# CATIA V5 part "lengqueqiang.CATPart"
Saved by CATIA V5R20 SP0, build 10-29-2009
Part number: lengqueqiang
Material "无"
Bounding box of the stored display mesh (mm): x -69 to 69, y -68.807 to 68.807, z -60 to 0
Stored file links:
  C:\Users\Administrator\Desktop\lengqueqiang.CATPart
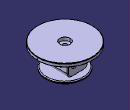
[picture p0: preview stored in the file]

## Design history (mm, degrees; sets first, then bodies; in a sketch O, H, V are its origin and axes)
Body1 (main body), material "无"
  Sketch1 on xy-plane, origin (0, 0, 0), H (1, 0, 0), V (0, 1, 0)
    circle A1 centre (0, 0) radius 69
    circle A2 centre (0, 0) radius 13
    point P1 (0, 13)
    radius A1 = 69
    radius A2 = 13
    coincidence: A2 P1, P1 V
  Pad1: profile Sketch1, direction (0, 0, -1), length 8
  Fillet1: radius 1, on edge [face of Pad1 from Sketch1.A1 | start face of Pad1]; edge [end face of Pad1 | face of Pad1 from Sketch1.A1]
  DatumCurve1
  Sketch2 on end face of Pad1, origin (0, 0, -8), H (1, 0, 0), V (0, 1, 0)
    circle A1 centre (0, 0) radius 47.9087
    projected circle E1 centre (0, 0) radius 5 from edge of DatumCurve1
  Pad2: profile Sketch2, direction (0, 0, -1), length 46
  Sketch3 on end face of Pad2, origin (0, 0, -54), H (1, 0, 0), V (0, 1, 0)
    line L1 (25.6616, 32.5842) -> (-25.6616, 32.5842)
    line L2 (-25.6616, 32.5842) -> (-25.6616, -32.5842)
    line L3 (-25.6616, -32.5842) -> (25.6616, -32.5842)
    line L4 (25.6616, -32.5842) -> (25.6616, 32.5842)
    horizontal: L1 H, L3 H
    vertical: L2 V, L4 V
    symmetry: L2 L4 V, L3 L1 H
  Pocket1: profile Sketch3, direction (0, 0, 1), up to end face of Pad1, outer side
  Sketch4 on face of Pocket1 from Sketch3.L3, origin (25.6616, -32.5842, -54), H (-1, 0, 0), V (0, 0, 1)
    point P1 (0, 32.5836)
    line L1 (0, 32.5836) -> (0, 11.4043)
    line L2 (11.4043, 0) -> (39.8486, 0)
    line L3 (51.2526, 11.404) -> (51.2526, 32.5836)
    arc A1 centre (11.4043, 11.4043) radius 11.4043 from (0, 11.4043) to (11.4043, 0) ccw
    arc A2 centre (39.8486, 11.404) radius 11.404 from (51.2526, 11.404) to (39.8486, 0) cw
    line L4 (0, 32.5836) -> (-7.3828, 32.5836)
    line L5 (-7.3828, 32.5836) -> (-7.3828, -3.4271)
    line L6 (-7.3828, -3.4271) -> (55.714, -3.4271)
    line L7 (55.714, -3.4271) -> (55.714, 32.5836)
    point P12 (55.714, 32.5836)
    line L8 (55.714, 32.5836) -> (51.2526, 32.5836)
    radius A1 = 11.4043
    radius A2 = 11.404
    coincidence: P1 V, L1 O, L2 O, P12 L4
    vertical: L1 V, L3 V, L5 V, L7 V
    horizontal: L2 H, L4 H, L6 H, L8 H
    tangency: A1 L1, A1 L2, A2 L3, A2 L2
  Pocket2: profile Sketch4, direction (0, -1, 0), up to face of Pocket1 from Sketch3.L1
  Fillet2: radius 2, on face of Pocket1 from Sketch3.L3; face of Pocket1 from Sketch3.L1
  Fillet3: radius 2, on edge [face of Pocket1 from Sketch3.L4 | face of Pad1]; edge [face of Pocket1 from Sketch3.L2 | face of Pad1]
  Sketch5 on face of Pocket2, origin (0, 0, -54), H (1, 0, 0), V (0, 1, 0)
    circle A1 centre (0, 0) radius 48.3895
  Pad3: profile Sketch5, direction (0, 0, -1), length 6
  Fillet4: radius 2, on edge [end face of Pad3 | face of Pad3 from Sketch5.A1]; edge [face of Pad3 from Sketch5.A1 | start face of Pad3]
  Sketch6 on face of Pocket2 from Sketch4.L3, origin (-25.591, -32.5842, -42.596), H (0, 0, 1), V (0, 1, 0)
    circle A1 centre (9.5436, 33.4497) radius 8.4277
    circle A2 centre (9.5436, 33.4497) radius 4.8742
  Pad4: profile Sketch6, direction (-1, 0, 0), length 5
  Fillet5: radius 1, on face of Pad4 from Sketch6.A1; end face of Pad4
  Sketch7 on face of Pocket1 from Sketch3.L1, origin (-25.6616, 32.5842, -54), H (1, 0, 0), V (0, 0, 1)
    circle A1 centre (15.647, 23.4128) radius 6.0872
    circle A2 centre (35.3317, 23.4128) radius 6.0872
  Pocket3: profile Sketch7, direction (0, -1, 0), length 15
  Fillet6: radius 1, on edge [face of Pocket3 from Sketch7.A1 | face of Pocket1 from Sketch3.L1]; edge [face of Pocket3 from Sketch7.A2 | face of Pocket1 from Sketch3.L1]
  Sketch8 on face of Pocket2 from Sketch4.L3, origin (-25.591, -32.5842, -42.596), H (0, 0, 1), V (0, 1, 0)
    projected circle E1 centre (9.5436, 33.4497) radius 5.8742 from edge [end face of Pad4 | face of Fillet5]
  Pocket4: profile Sketch8, direction (1, 0, 0), through (limit type 3)
  Sketch9 on face of Pocket1 from Sketch3.L4, origin (25.6616, 32.5842, -54), H (0, -1, 0), V (0, 0, 1)
    circle A1 centre (45.8595, 20.5274) radius 2.1606
    circle A2 centre (18.8662, 20.5274) radius 2.1606
  Pocket5: profile Sketch9, direction (-1, 0, 0), length 6
  Fillet7: radius 1, on edge [face of Pocket5 from Sketch9.A2 | face of Pocket1 from Sketch3.L4]; edge [face of Pocket4 from Sketch8.E1 | face of Pocket1 from Sketch3.L4]; edge [face of Pocket5 from Sketch9.A1 | face of Pocket1 from Sketch3.L4]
